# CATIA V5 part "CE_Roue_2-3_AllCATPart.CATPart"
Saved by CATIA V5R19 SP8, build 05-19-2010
Part number: CE10_Roue_2-3_AllCATPart
Bounding box of the stored display mesh (mm): x -86.109 to -44.587, y 96.875 to 135.736, z 84.648 to 115.601
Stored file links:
  D:\Documents\1_Travail\1 - ac-limoges.fr\ac-limoges.fr\Emmanuel Maynard - STI2D_Turgot\2 -2I2D\1_SEQUENCE_ Tapis_de_course\3- Spécificités\Spé_ITEC\3-Pente\Tapis_TC520B_Pente\CE_Roue_2-3_AllCATPart.CATPart
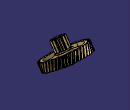
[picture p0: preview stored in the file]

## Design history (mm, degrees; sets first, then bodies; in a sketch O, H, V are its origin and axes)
AxisSystem1: origin (0, 0, 0), X (1, 0, 0), Y (0, 1, 0), Z (0, 0, 1)
Body1 (main body)
Body2 "Roue_3.1\\Corps principal"
  Solid1: solid without history
Body3 "Roue 2.1\\Corps principal"
  Solid2 "Solide.1": solid without history
  Plane1 "Plan.2": stored without definition
Body4 "Cale_R2-3.1\\Corps principal"
  Solid3 "Solide.1": solid without history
